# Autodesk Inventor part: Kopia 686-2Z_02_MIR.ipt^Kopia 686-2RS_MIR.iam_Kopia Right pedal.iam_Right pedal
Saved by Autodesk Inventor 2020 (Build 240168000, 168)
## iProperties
Created: 2017-10
Part Number: Kopia 686-2Z_02_MIR.ipt^Kopia 686-2RS_MIR.iam_Kopia Right pedal.iam_Right pedal
Material: Ogólny
Document SubType Name: Modeling
Designer: Tomasz
Density: 1 g/cm^3
Appearance: Domyślna
Sending System: SolidWorks 2017
Last Author: Tomasz
Last Saved: 2017-10-01
Author: Tomasz
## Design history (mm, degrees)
